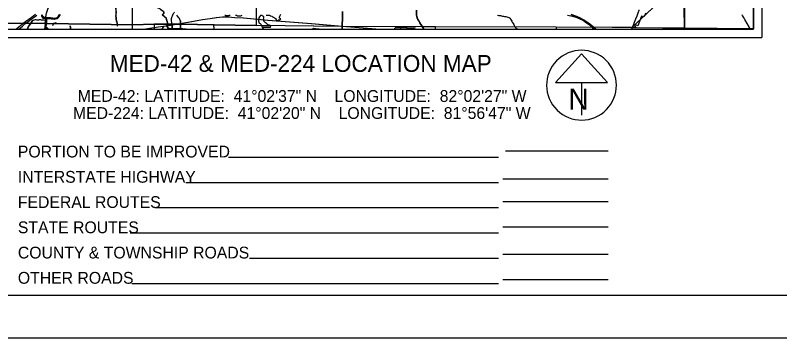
# Model space of a CAD drawing. Extents: x 0 to 34, y 0 to 22.
# Drawn here: x 17.63 to 26.7, y 0 to 3.83 of the extents above; entities that cross this region are included whole.
import ezdxf

# ---------------------------------------------------------------- set-up
doc = ezdxf.new("R2010")
doc.units = 0
for name, color, linetype in [('GM_X_City_Street', 7, 'Continuous'), ('GM_X_Corporation', 7, 'Continuous'), ('GM_X_County_Road', 7, 'Continuous'), ('GM_X_Interstate_Route', 7, 'Continuous'), ('GM_X_Minor_Lake', 7, 'Continuous'), ('GM_X_Minor_River', 7, 'Continuous'), ('GM_X_Rail_Line', 7, 'Continuous'), ('GM_X_State_Route', 7, 'Continuous'), ('GM_X_Township_Road', 7, 'Continuous'), ('SH_Border', 7, 'Continuous'), ('SH_Cut_Line', 7, 'Continuous'), ('SH_Data', 7, 'Continuous'), ('SH_Text', 7, 'Continuous')]:
    doc.layers.add(name, color=color, linetype=linetype)

msp = doc.modelspace()

# ---------------------------------------------------------------- linework, layer by layer
at = {"layer": 'GM_X_City_Street'}
for points in [[(22.1325, 3.6647), (22.1325, 3.6648), (22.1324, 3.6711), (22.1326, 3.6739), (22.133, 3.676), (22.1336, 3.6775), (22.1346, 3.6792), (22.1358, 3.6806), (22.1373, 3.682)], [(22.1373, 3.682), (22.1403, 3.6834), (22.1428, 3.6842), (22.144, 3.6844), (22.1452, 3.6846), (22.148, 3.6847), (22.1619, 3.6846), (22.1836, 3.6843), (22.2039, 3.6841), (22.2486, 3.6838), (22.2735, 3.6835), (22.2788, 3.6834), (22.2948, 3.6833), (22.355, 3.6828), (22.3591, 3.6826), (22.3626, 3.6824), (22.3665, 3.6821), (22.3777, 3.6836)], [(22.2043, 3.6647), (22.2043, 3.6652), (22.204, 3.6805), (22.2039, 3.6841)], [(22.2795, 3.6647), (22.279, 3.6786), (22.2788, 3.6834)]]:
    msp.add_lwpolyline(points, dxfattribs=at)
at = {"layer": 'GM_X_Corporation'}
msp.add_lwpolyline([(25.1115, 3.8574), (25.0873, 3.8111), (25.061, 3.8214), (25.0144, 3.7036), (24.967, 3.7237), (24.9594, 3.7058), (24.977, 3.7053), (24.9927, 3.6854), (24.987, 3.6806), (24.949, 3.6808), (24.9379, 3.685), (24.7133, 3.6874), (24.0458, 3.6895), (24.0466, 3.6647), (25.3161, 3.6647), (25.3153, 3.6789), (25.5717, 3.6776), (25.5644, 3.9211)], dxfattribs=at)
msp.add_lwpolyline([(19.2746, 3.6647), (19.988, 3.6647), (19.9851, 3.7176), (19.5897, 3.7242), (19.4866, 3.7244), (19.274, 3.7238)], close=True, dxfattribs=at)
at = {"layer": 'GM_X_County_Road'}
for points in [[(19.4836, 3.7974), (19.4856, 3.8064), (19.4882, 3.8153), (19.4922, 3.8258), (19.4969, 3.8369), (19.5021, 3.8472), (19.5073, 3.855), (19.5143, 3.8641), (19.5178, 3.8683)], [(21.5083, 3.7021), (21.5085, 3.7215), (21.5101, 3.7869), (21.5108, 3.8253), (21.5121, 3.8765)], [(21.5116, 3.7021), (21.5118, 3.7215), (21.5133, 3.7869), (21.5141, 3.8253), (21.5153, 3.8765)], [(22.4568, 3.6984), (22.4559, 3.6999), (22.4423, 3.7221), (22.4308, 3.7405), (22.4194, 3.7589), (22.4061, 3.7814), (22.4023, 3.7887), (22.3989, 3.7968), (22.3964, 3.8034), (22.395, 3.8078), (22.3936, 3.8126), (22.3924, 3.8178), (22.3916, 3.8231), (22.3909, 3.8276), (22.3903, 3.8341), (22.3902, 3.8542), (22.3905, 3.8723), (22.3906, 3.8912)], [(22.46, 3.6984), (22.4592, 3.6999), (22.4455, 3.7221), (22.4341, 3.7405), (22.4227, 3.7589), (22.4094, 3.7814), (22.4055, 3.7887), (22.4022, 3.7968), (22.3997, 3.8034), (22.3983, 3.8078), (22.3968, 3.8126), (22.3957, 3.8178), (22.3949, 3.8231), (22.3942, 3.8276), (22.3935, 3.8341), (22.3935, 3.8542), (22.3938, 3.8723), (22.3939, 3.8912)], [(19.4873, 3.7176), (19.4861, 3.7268), (19.4854, 3.7364), (19.4825, 3.7695), (19.482, 3.7794), (19.4823, 3.7892), (19.4832, 3.7954), (19.4836, 3.7974)], [(21.509, 3.6647), (21.5089, 3.6683), (21.5083, 3.7021)], [(21.5122, 3.6647), (21.5122, 3.6683), (21.5116, 3.7021)], [(22.4779, 3.6647), (22.4659, 3.6841), (22.4568, 3.6984)], [(22.4812, 3.6647), (22.4692, 3.6841), (22.46, 3.6984)]]:
    msp.add_lwpolyline(points, dxfattribs=at)
at = {"layer": 'GM_X_Interstate_Route'}
for points in [[(17.7127, 3.7283), (17.7479, 3.7563), (17.7503, 3.7582), (17.7865, 3.7854), (17.8303, 3.8168), (17.8684, 3.8428)], [(17.7413, 3.7278), (17.7743, 3.7536), (17.8152, 3.7837), (17.8516, 3.8096), (17.8848, 3.8329)], [(17.6365, 3.6647), (17.6434, 3.6708), (17.6738, 3.6972), (17.7127, 3.7283)], [(17.6676, 3.6647), (17.6845, 3.6792), (17.7132, 3.7031), (17.7413, 3.7278)]]:
    msp.add_lwpolyline(points, dxfattribs=at)
at = {"layer": 'GM_X_Minor_Lake'}
for points in [[(20.1136, 3.8355), (20.1269, 3.8292), (20.1402, 3.8286), (20.1527, 3.8295), (20.1656, 3.8297), (20.1781, 3.8348)], [(20.1136, 3.8355), (20.1269, 3.8292), (20.1402, 3.8286), (20.1527, 3.8295), (20.1656, 3.8297), (20.1781, 3.8348)], [(20.2399, 3.8337), (20.2532, 3.8301), (20.2665, 3.8257), (20.2794, 3.8236), (20.2935, 3.8238), (20.306, 3.8258), (20.3188, 3.8313)], [(20.2399, 3.8337), (20.2532, 3.8301), (20.2665, 3.8257), (20.2794, 3.8236), (20.2935, 3.8238), (20.306, 3.8258), (20.3188, 3.8313)], [(20.5545, 3.8283), (20.5372, 3.8265), (20.5264, 3.8135), (20.5194, 3.8008), (20.5176, 3.7902), (20.5155, 3.7765), (20.5145, 3.7635), (20.5166, 3.7514), (20.5198, 3.7393), (20.5335, 3.7311), (20.5446, 3.7214), (20.5579, 3.6907), (20.6552, 3.69)], [(20.5547, 3.8283), (20.5372, 3.8265), (20.5264, 3.8135), (20.5194, 3.8008), (20.5176, 3.7902), (20.5155, 3.7765), (20.5145, 3.7635), (20.5166, 3.7514), (20.5198, 3.7393), (20.5335, 3.7311), (20.5446, 3.7214), (20.5579, 3.6907), (20.6549, 3.69)], [(20.6552, 3.69), (20.659, 3.7069), (20.6464, 3.7124), (20.6335, 3.7126), (20.6201, 3.7216), (20.6105, 3.7329), (20.5986, 3.7403), (20.5875, 3.75), (20.5787, 3.7602), (20.5755, 3.7731), (20.5749, 3.786), (20.5766, 3.7997), (20.5757, 3.8141), (20.5545, 3.8283)], [(20.6551, 3.6897), (20.659, 3.7069), (20.6464, 3.7124), (20.6335, 3.7126), (20.6201, 3.7216), (20.6105, 3.7329), (20.5986, 3.7403), (20.5875, 3.75), (20.5787, 3.7602), (20.5755, 3.7731), (20.5749, 3.786), (20.5766, 3.7997), (20.5757, 3.8141), (20.555, 3.8279)], [(20.6062, 3.8331), (20.6183, 3.8306), (20.632, 3.8315), (20.6453, 3.8306), (20.6582, 3.8254), (20.6708, 3.8187), (20.6807, 3.8132), (20.6937, 3.8073), (20.7059, 3.8021), (20.7178, 3.7928), (20.7217, 3.781), (20.7291, 3.769), (20.742, 3.7669), (20.7533, 3.775), (20.7669, 3.7748), (20.7774, 3.7878), (20.7648, 3.7956), (20.7623, 3.8089), (20.7659, 3.8219), (20.7785, 3.8445)], [(20.6062, 3.8331), (20.6183, 3.8306), (20.632, 3.8315), (20.6453, 3.8306), (20.6582, 3.8254), (20.6708, 3.8187), (20.6807, 3.8132), (20.6937, 3.8073), (20.7059, 3.8021), (20.7178, 3.7928), (20.7217, 3.781), (20.7291, 3.769), (20.742, 3.7669), (20.7533, 3.775), (20.7669, 3.7748), (20.7774, 3.7878), (20.7648, 3.7956), (20.7623, 3.8089), (20.7659, 3.8219), (20.7786, 3.8445)], [(20.5574, 3.6905), (20.5712, 3.671), (20.5762, 3.6647)], [(20.6552, 3.6898), (20.5574, 3.6905)]]:
    msp.add_lwpolyline(points, dxfattribs=at)
at = {"layer": 'GM_X_Minor_River'}
for points in [[(18.8064, 3.957), (18.8138, 3.9388), (18.8166, 3.9251), (18.8175, 3.9115), (18.8192, 3.8986), (18.8193, 3.886), (18.8222, 3.8724), (18.8216, 3.8587), (18.8195, 3.8462), (18.8193, 3.8325), (18.8187, 3.8195), (18.82, 3.8059), (18.8205, 3.7926), (18.8226, 3.7789), (18.8262, 3.7657), (18.8298, 3.7517), (18.8349, 3.7381), (18.8335, 3.7248), (18.8346, 3.7025)], [(18.8097, 3.957), (18.817, 3.9388), (18.8198, 3.9251), (18.8208, 3.9115), (18.8225, 3.8986), (18.8226, 3.886), (18.8254, 3.8724), (18.8249, 3.8587), (18.8227, 3.8462), (18.8225, 3.8325), (18.8219, 3.8195), (18.8233, 3.8059), (18.8238, 3.7926), (18.8259, 3.7789), (18.8295, 3.7657), (18.833, 3.7517), (18.8381, 3.7381), (18.8368, 3.7248), (18.8379, 3.7025)], [(19.425, 3.6983), (19.4312, 3.7161), (19.4344, 3.7291), (19.4343, 3.7428), (19.4303, 3.7556), (19.4241, 3.7677), (19.4209, 3.7813), (19.4184, 3.795), (19.4077, 3.8051), (19.3943, 3.8156), (19.3825, 3.8223), (19.3751, 3.8336), (19.3787, 3.8458), (19.3892, 3.855), (19.3921, 3.868), (19.3799, 3.8777), (19.3703, 3.8833), (19.3577, 3.8922), (19.3462, 3.9039), (19.3335, 3.9124), (19.3172, 3.9145)], [(19.4283, 3.6983), (19.4345, 3.7161), (19.4377, 3.7291), (19.4375, 3.7428), (19.4336, 3.7556), (19.4274, 3.7677), (19.4242, 3.7813), (19.4217, 3.795), (19.411, 3.8051), (19.3976, 3.8156), (19.3857, 3.8223), (19.3784, 3.8336), (19.382, 3.8458), (19.3925, 3.855), (19.3954, 3.868), (19.3831, 3.8777), (19.3736, 3.8833), (19.3609, 3.8922), (19.3494, 3.9039), (19.3368, 3.9124), (19.3204, 3.9145)], [(17.9392, 3.8348), (17.9398, 3.8219), (17.9449, 3.8094), (17.9549, 3.7982), (17.9678, 3.796), (17.9799, 3.7943), (17.9924, 3.7941), (18.0046, 3.7935), (18.0167, 3.7921), (18.0262, 3.7907), (18.0403, 3.7909), (18.0539, 3.788), (18.0634, 3.7866), (18.076, 3.7868), (18.0885, 3.7851), (18.1014, 3.7871), (18.115, 3.7907), (18.1267, 3.792), (18.1379, 3.8036), (18.1469, 3.8147), (18.1528, 3.8281), (18.161, 3.8396)], [(17.9425, 3.8348), (17.943, 3.8219), (17.9481, 3.8094), (17.9581, 3.7982), (17.971, 3.796), (17.9832, 3.7943), (17.9957, 3.7941), (18.0079, 3.7935), (18.02, 3.7921), (18.0295, 3.7907), (18.0435, 3.7909), (18.0572, 3.788), (18.0667, 3.7866), (18.0792, 3.7868), (18.0918, 3.7851), (18.1046, 3.7871), (18.1182, 3.7907), (18.13, 3.792), (18.1412, 3.8036), (18.1501, 3.8147), (18.156, 3.8281), (18.1642, 3.8396)], [(18.1439, 3.8371), (18.1392, 3.8241), (18.1314, 3.8111), (18.1217, 3.8011), (18.1088, 3.7948), (18.0964, 3.7931), (18.0819, 3.793), (18.069, 3.7947), (18.0576, 3.7964), (18.0436, 3.7985), (18.0311, 3.7984), (18.0182, 3.7997), (18.006, 3.8011), (17.9946, 3.8025), (17.9813, 3.8027), (17.9677, 3.8025), (17.9547, 3.8118), (17.9469, 3.825), (17.9487, 3.8376)], [(18.1472, 3.8371), (18.1424, 3.8241), (18.1347, 3.8111), (18.1249, 3.8011), (18.1121, 3.7948), (18.0996, 3.7931), (18.0852, 3.793), (18.0723, 3.7947), (18.0609, 3.7964), (18.0468, 3.7985), (18.0343, 3.7984), (18.0214, 3.7997), (18.0093, 3.8011), (17.9979, 3.8025), (17.9846, 3.8027), (17.971, 3.8025), (17.958, 3.8118), (17.9502, 3.825), (17.9519, 3.8376)], [(23.3509, 3.8327), (23.3646, 3.8299), (23.3761, 3.8278), (23.3856, 3.8264), (23.3978, 3.8243), (23.4108, 3.8219), (23.423, 3.8183), (23.4345, 3.8166), (23.4482, 3.8149), (23.462, 3.8113), (23.4738, 3.8089), (23.4864, 3.806), (23.4995, 3.7967), (23.5069, 3.7854), (23.5132, 3.7734), (23.5191, 3.7602), (23.5266, 3.747), (23.5355, 3.7335), (23.5426, 3.7207), (23.5504, 3.7075), (23.5583, 3.6939), (23.5684, 3.6814), (23.5823, 3.669)], [(17.9949, 3.7673), (17.9768, 3.7699), (17.9639, 3.7717), (17.9514, 3.773), (17.9392, 3.7744), (17.926, 3.7754), (17.9127, 3.7756), (17.8991, 3.7735), (17.8858, 3.7741), (17.8736, 3.7758), (17.8615, 3.7753), (17.8475, 3.7736), (17.8354, 3.7696), (17.8238, 3.76), (17.8148, 3.7473), (17.8086, 3.7351), (17.7897, 3.7097)], [(17.9982, 3.7673), (17.9801, 3.7699), (17.9672, 3.7717), (17.9547, 3.773), (17.9425, 3.7744), (17.9292, 3.7754), (17.916, 3.7756), (17.9023, 3.7735), (17.8891, 3.7741), (17.8769, 3.7758), (17.8648, 3.7753), (17.8508, 3.7736), (17.8387, 3.7696), (17.827, 3.76), (17.8181, 3.7473), (17.8118, 3.7351), (17.7929, 3.7097)], [(17.9997, 3.7923), (17.9957, 3.7793), (17.9947, 3.766), (17.9952, 3.7538), (17.9935, 3.7401), (17.9925, 3.7306), (17.9886, 3.7085)], [(18.0029, 3.7923), (17.9989, 3.7793), (17.998, 3.766), (17.9985, 3.7538), (17.9968, 3.7401), (17.9958, 3.7306), (17.9919, 3.7085)], [(18.108, 3.7405), (18.0959, 3.7377), (18.0839, 3.7322), (18.0722, 3.7263), (18.068, 3.7081)], [(18.1113, 3.7405), (18.0992, 3.7377), (18.0871, 3.7322), (18.0754, 3.7263), (18.0712, 3.7081)], [(17.7897, 3.7097), (17.7875, 3.7067), (17.7819, 3.6961), (17.7773, 3.6862), (17.7736, 3.6756), (17.7715, 3.6647)], [(17.7929, 3.7097), (17.7908, 3.7067), (17.7851, 3.6961), (17.7806, 3.6862), (17.7768, 3.6756), (17.7748, 3.6647)], [(17.9886, 3.7085), (17.9881, 3.7005), (17.987, 3.6899), (17.987, 3.6789), (17.9863, 3.6663), (17.9863, 3.6647)], [(17.9872, 3.6911), (17.9984, 3.6846), (18.0087, 3.6743), (18.0185, 3.6667), (18.0233, 3.6647)], [(17.9919, 3.7085), (17.9914, 3.7005), (17.9903, 3.6899), (17.9903, 3.6789), (17.9896, 3.6663), (17.9896, 3.6647)], [(17.9904, 3.6911), (18.0017, 3.6846), (18.0119, 3.6743), (18.0218, 3.6667), (18.0266, 3.6647)], [(18.2744, 3.7067), (18.2781, 3.6868), (18.2801, 3.6754), (18.2822, 3.6647)], [(18.2777, 3.7067), (18.2814, 3.6868), (18.2833, 3.6754), (18.2855, 3.6647)], [(19.3834, 3.6986), (19.3689, 3.6735), (19.3678, 3.6647)], [(19.3866, 3.6986), (19.3721, 3.6735), (19.3711, 3.6647)], [(19.425, 3.6983), (19.4383, 3.6785)], [(19.4282, 3.6983), (19.4415, 3.6785)], [(19.4383, 3.6785), (19.4508, 3.6766), (19.4603, 3.6751), (19.4713, 3.6744), (19.4811, 3.6744), (19.4921, 3.6736), (19.5058, 3.6733), (19.5164, 3.6737), (19.5278, 3.6737), (19.5411, 3.6733), (19.5558, 3.673), (19.5672, 3.673), (19.5775, 3.6726), (19.5919, 3.6722), (19.6029, 3.6719), (19.6135, 3.6711), (19.6233, 3.6704), (19.6374, 3.6689), (19.6491, 3.6677), (19.6601, 3.6659), (19.667, 3.6647)], [(19.4415, 3.6785), (19.4541, 3.6766), (19.4635, 3.6751), (19.4745, 3.6744), (19.4844, 3.6744), (19.4954, 3.6736), (19.509, 3.6733), (19.5197, 3.6737), (19.531, 3.6737), (19.5443, 3.6733), (19.5591, 3.673), (19.5705, 3.673), (19.5807, 3.6726), (19.5951, 3.6722), (19.6061, 3.6719), (19.6168, 3.6711), (19.6266, 3.6704), (19.6407, 3.6689), (19.6524, 3.6677), (19.6634, 3.6659), (19.6703, 3.6647)], [(21.144, 3.6647), (21.1553, 3.6713), (21.1659, 3.6766), (21.1776, 3.6755), (21.1879, 3.6736), (21.1978, 3.6714), (21.2076, 3.6695), (21.2209, 3.6691), (21.2307, 3.6687), (21.241, 3.6676), (21.2524, 3.6657), (21.2586, 3.6647)], [(23.5846, 3.6647), (23.584, 3.6661), (23.5823, 3.669)]]:
    msp.add_lwpolyline(points, dxfattribs=at)
at = {"layer": 'GM_X_Rail_Line'}
for p, q in [((17.9817, 3.727), (17.9736, 3.6647)), ((24.4793, 3.6829), (24.4989, 3.6647))]:
    msp.add_line(p, q, dxfattribs=at)
for points in [[(26.39, 3.6678), (26.39, 8.7517), (26.3812, 8.7517), (25.61, 8.7495), (25.6021, 8.0258), (25.6016, 7.958), (25.5949, 6.9989), (25.5948, 6.9859), (25.5947, 6.9673), (25.5942, 6.8999), (25.594, 6.873), (25.5922, 6.6163), (25.5923, 6.6046), (25.5921, 6.5988), (25.5865, 5.8006), (25.582, 5.143), (25.5795, 4.789), (25.5717, 3.6776), (26.3477, 3.6686)], [(19.4902, 3.6647), (22.6135, 3.6647), (22.6135, 3.6939), (22.459, 3.6944), (21.5082, 3.6961), (20.4887, 3.7091), (19.9851, 3.7176), (19.5897, 3.7242), (19.4866, 3.7244), (19.4876, 3.7147), (19.4887, 3.6993), (19.4896, 3.6775), (19.4902, 3.6648)], [(19.59, 3.7242), (19.59, 3.6647), (25.5725, 3.6647), (25.5717, 3.6776), (25.3153, 3.6789), (24.987, 3.6806), (24.949, 3.6808), (24.9379, 3.685), (24.7133, 3.6874), (24.0458, 3.6895), (22.4622, 3.6944), (21.5114, 3.6961), (20.492, 3.7091), (19.9883, 3.7176), (19.593, 3.7242)], [(25.5725, 3.6647), (26.39, 3.6647), (26.39, 3.6678), (26.3477, 3.6686), (25.5717, 3.6776)]]:
    msp.add_lwpolyline(points, close=True, dxfattribs=at)
for points in [[(24.9499, 3.6844), (24.9615, 3.7017), (24.9988, 3.7358), (25.7536, 4.446), (26.1804, 4.8358), (26.3268, 4.9703), (26.3834, 5.0214), (26.39, 5.0313)], [(17.9817, 3.727), (17.9899, 3.8116), (17.9993, 3.8573), (18.018, 3.9161), (18.2628, 4.3545), (18.2981, 4.4174), (18.3137, 4.4462), (18.3213, 4.4815), (18.3297, 4.5431), (18.33, 4.5513)], [(17.4277, 3.7348), (17.7194, 3.7358), (17.7524, 3.7356), (19.0185, 3.7189), (19.274, 3.7238), (19.4866, 3.7244), (19.5897, 3.7242), (19.9851, 3.7176), (20.4887, 3.7091), (20.4914, 4.1177)], [(19.4462, 3.7106), (19.6767, 3.7485), (19.8481, 3.779), (19.9384, 3.7943), (20.0124, 3.8037), (20.0852, 3.8107), (20.1532, 3.8107), (20.2319, 3.806), (20.3375, 3.7989), (20.6251, 3.7742), (21.1404, 3.7341), (21.4605, 3.7054)], [(19.59, 3.7337), (19.6799, 3.7485), (19.8513, 3.779), (19.9417, 3.7943), (20.0157, 3.8037), (20.0884, 3.8107), (20.1565, 3.8107), (20.2351, 3.806), (20.3408, 3.7989), (20.6283, 3.7742), (21.1436, 3.7341), (21.4638, 3.7054)], [(24.1808, 3.8334), (24.2214, 3.8252), (24.2412, 3.82), (24.2921, 3.8038), (24.3363, 3.7846), (24.3695, 3.7677), (24.4089, 3.7419), (24.4408, 3.7184), (24.4793, 3.6829)], [(24.2226, 3.8408), (24.2621, 3.8266), (24.2855, 3.8174), (24.3211, 3.8016), (24.3594, 3.7816), (24.3823, 3.7683), (24.4296, 3.7379), (24.4635, 3.7115), (24.4884, 3.6902)], [(24.2236, 3.8434), (24.2631, 3.8293), (24.2866, 3.82), (24.3223, 3.8041), (24.3607, 3.784), (24.3838, 3.7707), (24.4312, 3.7402), (24.4653, 3.7137), (24.4902, 3.6923)], [(15.8135, 3.6647), (19.4902, 3.6647), (19.4902, 3.6648), (19.4896, 3.6775), (19.4887, 3.6993), (19.4876, 3.7147), (19.4866, 3.7244), (19.274, 3.7238), (19.0185, 3.7189), (17.7524, 3.7356), (17.7194, 3.7358), (17.4277, 3.7348)], [(19.1487, 3.6647), (19.3229, 3.6951), (19.4462, 3.7106)], [(21.4605, 3.7054), (21.9538, 3.6658), (21.9669, 3.6647)], [(21.4638, 3.7054), (21.957, 3.6658), (21.9702, 3.6647)], [(24.4884, 3.6902), (24.515, 3.6671), (24.5175, 3.6647)], [(24.4902, 3.6923), (24.5133, 3.6718), (24.521, 3.6647)], [(24.9499, 3.6844), (24.9472, 3.6803), (24.9408, 3.6647)]]:
    msp.add_lwpolyline(points, dxfattribs=at)
at = {"layer": 'GM_X_State_Route'}
for p, q in [((24.9609, 3.7081), (24.9685, 3.7268)), ((24.9437, 3.6647), (24.9508, 3.6836)), ((24.9508, 3.6836), (24.9609, 3.7081))]:
    msp.add_line(p, q, dxfattribs=at)
for points in [[(19.5896, 3.7167), (19.5893, 3.7335), (19.5888, 3.7476), (19.5885, 3.7529), (19.5881, 3.7565), (19.5875, 3.7601), (19.5868, 3.7643), (19.5859, 3.7681), (19.5845, 3.7728), (19.5823, 3.7787), (19.5798, 3.7843), (19.5769, 3.7896), (19.5746, 3.7929), (19.572, 3.7967), (19.568, 3.8021), (19.5457, 3.8314)], [(24.9685, 3.7268), (24.9776, 3.749), (24.9937, 3.7888), (25.008, 3.8258), (25.0211, 3.8604), (25.0324, 3.8933), (25.0325, 3.8936)], [(19.5929, 3.7167), (19.5926, 3.7335), (19.5921, 3.7476), (19.5917, 3.7529), (19.5914, 3.7565), (19.5908, 3.7601), (19.5901, 3.7643), (19.59, 3.7646)], [(19.59, 3.6813), (19.5901, 3.6873), (19.5901, 3.7042), (19.5896, 3.7167)], [(19.59, 3.6647), (19.59, 3.6764), (19.59, 3.6813)], [(19.5933, 3.6813), (19.5933, 3.6873), (19.5933, 3.7042), (19.5929, 3.7167)], [(19.5933, 3.6647), (19.5933, 3.6764), (19.5933, 3.6813)]]:
    msp.add_lwpolyline(points, dxfattribs=at)
at = {"layer": 'GM_X_Township_Road'}
msp.add_line((26.349, 3.6647), (26.3447, 3.6773), dxfattribs=at)
for points in [[(19.0187, 3.7176), (19.0181, 3.7594), (19.018, 3.7975), (19.0177, 3.8369), (19.0173, 3.8762), (19.0168, 3.9104), (19.0166, 3.9369), (19.0162, 3.9796), (19.016, 4.0855)], [(26.3447, 3.6773), (26.3434, 3.6805), (26.3412, 3.6844), (26.2869, 3.7807), (26.2707, 3.8091), (26.2592, 3.8289), (26.2557, 3.8357)], [(19.0197, 3.6647), (19.0195, 3.6828), (19.0187, 3.7176)]]:
    msp.add_lwpolyline(points, dxfattribs=at)
at = {"layer": 'SH_Border'}
msp.add_lwpolyline([(1.5, 21.5), (33.5, 21.5), (33.5, 0.5), (1.5, 0.5)], close=True, dxfattribs=at)
at = {"layer": 'SH_Cut_Line'}
for points in [[(0, 0), (34, 0), (34, 22), (0, 22)], [(19.59, 3.7242), (19.59, 3.6647), (26.39, 3.6647), (26.39, 3.6678), (26.3477, 3.6686), (25.5717, 3.6776), (25.3153, 3.6789), (24.987, 3.6806), (24.949, 3.6808), (24.9379, 3.685), (24.7133, 3.6874), (24.0458, 3.6895), (22.4622, 3.6944), (21.5114, 3.6961), (20.492, 3.7091), (19.9883, 3.7176), (19.593, 3.7242)]]:
    msp.add_lwpolyline(points, close=True, dxfattribs=at)
msp.add_lwpolyline([(15.8135, 3.6647), (22.6135, 3.6647), (22.6135, 3.6939), (22.459, 3.6944), (21.5082, 3.6961), (20.4887, 3.7091), (19.9851, 3.7176), (19.5897, 3.7242), (19.4866, 3.7244), (19.274, 3.7238), (19.0185, 3.7189), (17.7524, 3.7356), (17.7194, 3.7358), (17.4277, 3.7348)], dxfattribs=at)
at = {"layer": 'SH_Data'}
for p, q in [((26.49, 10.5678), (26.49, 3.5678)), ((26.39, 10.4678), (26.39, 3.6678)), ((15.8135, 3.6647), (22.6135, 3.6647)), ((22.6135, 3.6647), (26.39, 3.6647)), ((15.7135, 3.5647), (26.49, 3.5647)), ((24.348, 3.3738), (24.0404, 3.0325)), ((24.6556, 3.0325), (24.348, 3.3738)), ((24.0404, 3.0325), (24.6556, 3.0325)), ((24.348, 3.0325), (24.348, 2.6458)), ((24.348, 3), (24.348, 3)), ((24.348, 3), (24.348, 3)), ((23.4461, 2.22), (24.6635, 2.22)), ((23.3635, 2.1414), (20.1571, 2.1414)), ((23.3635, 1.8414), (19.653, 1.8414)), ((24.6635, 1.8855), (23.4135, 1.8855)), ((24.6635, 1.6138), (23.4135, 1.6138)), ((23.3635, 1.5414), (19.2827, 1.5414)), ((24.6635, 1.3138), (23.4135, 1.3138)), ((23.3635, 1.2414), (18.9923, 1.2414)), ((23.3635, 0.9414), (20.4087, 0.9414)), ((24.6635, 0.987), (23.4135, 0.987)), ((23.3635, 0.6414), (19.0106, 0.6414)), ((24.6635, 0.687), (23.4135, 0.687))]:
    msp.add_line(p, q, dxfattribs=at)
msp.add_arc((24.348, 3), 0.4148, 129.77984, 129.76332, dxfattribs=at)

# ---------------------------------------------------------------- texts
msp.add_text('N', height=0.25, dxfattribs=at).set_placement((24.1927, 2.7087))
at = {"layer": 'SH_Text'}
for s, height, p in [('MED-42 & MED-224 LOCATION MAP', 0.2, (18.7491, 3.1585)), ('MED-42: LATITUDE:  41°02\'37" N    LONGITUDE:  82°02\'27" W', 0.14, (18.3678, 2.8017)), ('MED-224: LATITUDE:  41°02\'20" N    LONGITUDE:  81°56\'47" W', 0.14, (18.312, 2.5992)), ('PORTION TO BE IMPROVED', 0.14, (17.6579, 2.1414)), ('INTERSTATE HIGHWAY', 0.14, (17.6579, 1.8414)), ('FEDERAL ROUTES', 0.14, (17.6579, 1.5414)), ('STATE ROUTES', 0.14, (17.6579, 1.2414)), ('COUNTY & TOWNSHIP ROADS', 0.14, (17.6579, 0.9414)), ('OTHER ROADS', 0.14, (17.6579, 0.6414))]:
    msp.add_text(s, height=height, dxfattribs=at).set_placement(p)

doc.saveas('drawing.dxf')
